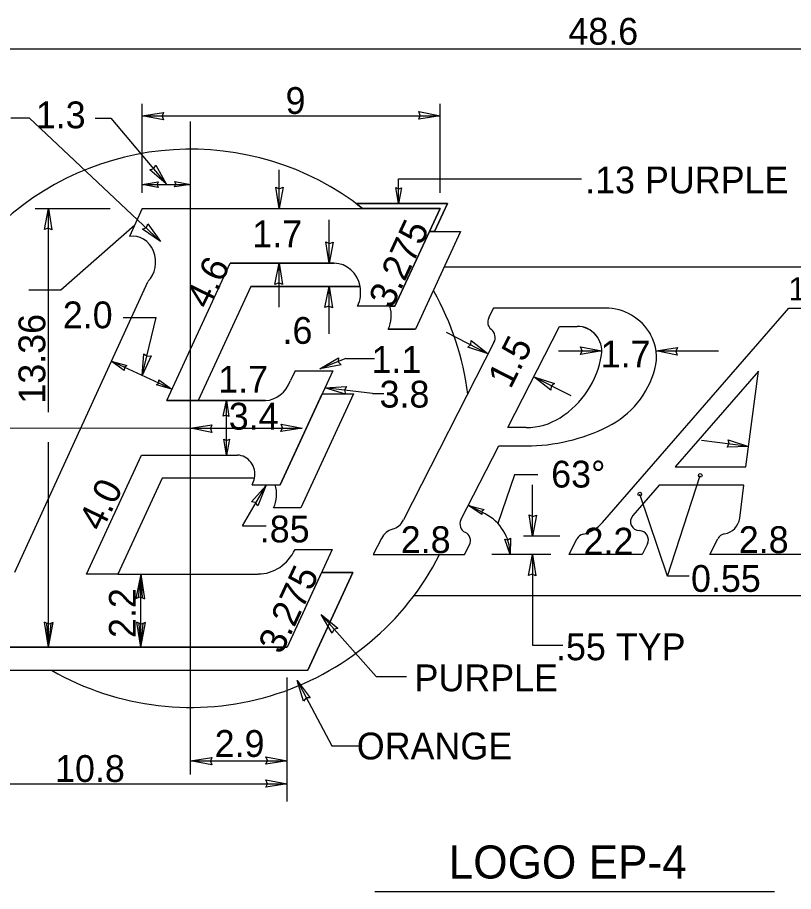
# Model space of a CAD drawing. Extents: x 10268197 to 10269179, y 2141503 to 2142677.
# Drawn here: x 10268503.98 to 10268524.24, y 2141999.29 to 2142022.12 of the extents above; entities that cross this region are included whole.
import ezdxf

# ---------------------------------------------------------------- set-up
doc = ezdxf.new("R2010")
doc.units = 0
for name, color, linetype in [('1', 7, 'Continuous'), ('21', 7, 'Continuous'), ('52', 7, 'Continuous'), ('NonPlottingEle_dp', 7, 'Continuous'), ('North Arrow', 7, 'Continuous')]:
    doc.layers.add(name, color=color, linetype=linetype)

msp = doc.modelspace()

# ---------------------------------------------------------------- linework, layer by layer
at = {"layer": '1'}
for p, q in [((10268499.274, 2142021.299), (10268540.97, 2142021.299)), ((10268507.237, 2142017.54), (10268507.237, 2142019.863)), ((10268515.011, 2142017.54), (10268515.011, 2142019.863)), ((10268506.005, 2142019.489), (10268506.417, 2142019.489)), ((10268506.417, 2142019.489), (10268507.862, 2142017.77)), ((10268507.237, 2142019.55), (10268515.011, 2142019.55)), ((10268508.5, 2142011.389), (10268508.5, 2142019.396)), ((10268510.808, 2142017.129), (10268510.808, 2142018.135)), ((10268507.237, 2142017.756), (10268508.5, 2142017.756)), ((10268513.926, 2142017.256), (10268513.926, 2142017.903)), ((10268513.926, 2142017.903), (10268518.702, 2142017.903)), ((10268504.437, 2142017.129), (10268506.399, 2142017.129)), ((10268504.789, 2142011.812), (10268504.789, 2142017.129)), ((10268512.99, 2142017.129), (10268512.824, 2142017.256)), ((10268512.824, 2142017.256), (10268515.208, 2142017.256)), ((10268515.011, 2142017.129), (10268512.99, 2142017.129)), ((10268514.733, 2142016.527), (10268515.011, 2142017.129)), ((10268515.208, 2142017.256), (10268514.871, 2142016.527)), ((10268505.111, 2142015.001), (10268507.044, 2142016.702)), ((10268512.115, 2142015.698), (10268512.115, 2142016.83)), ((10268513.832, 2142014.579), (10268514.733, 2142016.527)), ((10268515.55, 2142016.527), (10268514.371, 2142013.976)), ((10268514.733, 2142016.527), (10268515.55, 2142016.527)), ((10268514.733, 2142016.527), (10268515.55, 2142016.527)), ((10268514.871, 2142016.527), (10268514.733, 2142016.527)), ((10268507.878, 2142012.117), (10268509.53, 2142015.698)), ((10268509.53, 2142015.698), (10268512.248, 2142015.698)), ((10268510.808, 2142014.552), (10268510.808, 2142015.698)), ((10268510.071, 2142015.095), (10268508.694, 2142012.117)), ((10268510.071, 2142015.095), (10268512.925, 2142015.095)), ((10268512.925, 2142015.095), (10268510.581, 2142015.095)), ((10268512.115, 2142013.852), (10268512.115, 2142015.095)), ((10268504.276, 2142015.001), (10268505.111, 2142015.001)), ((10268513.702, 2142014.579), (10268513.832, 2142014.579)), ((10268506.737, 2142014.281), (10268507.602, 2142014.281)), ((10268507.231, 2142012.771), (10268507.602, 2142014.281)), ((10268514.371, 2142013.976), (10268513.66, 2142013.976)), ((10268515.173, 2142013.896), (10268516.272, 2142013.336)), ((10268512.555, 2142013.211), (10268511.875, 2142012.94)), ((10268512.555, 2142013.211), (10268513.297, 2142013.214)), ((10268518.106, 2142013.407), (10268519.236, 2142013.407)), ((10268520.654, 2142013.407), (10268522.28, 2142013.407)), ((10268508.013, 2142012.41), (10268506.423, 2142013.143)), ((10268517.461, 2142012.731), (10268518.423, 2142012.241)), ((10268510.836, 2142009.913), (10268511.933, 2142012.288)), ((10268512.75, 2142012.288), (10268511.376, 2142009.312)), ((10268511.933, 2142012.288), (10268512.75, 2142012.288)), ((10268513.245, 2142012.297), (10268512.008, 2142012.449)), ((10268513.245, 2142012.297), (10268513.54, 2142012.298)), ((10268508.694, 2142012.117), (10268507.878, 2142012.117)), ((10268509.433, 2142010.686), (10268509.433, 2142012.117)), ((10268508.5, 2142011.389), (10268501.211, 2142011.378)), ((10268508.5, 2142002.35), (10268508.5, 2142011.389)), ((10268508.5, 2142011.389), (10268511.416, 2142011.389)), ((10268504.789, 2142005.676), (10268504.789, 2142011.028)), ((10268523.068, 2142010.914), (10268521.837, 2142011.074)), ((10268505.783, 2142007.584), (10268507.216, 2142010.686)), ((10268507.216, 2142010.686), (10268509.722, 2142010.686)), ((10268507.757, 2142010.083), (10268506.6, 2142007.584)), ((10268510.167, 2142010.083), (10268507.757, 2142010.083)), ((10268516.956, 2142010.178), (10268516.523, 2142008.904)), ((10268517.567, 2142010.178), (10268516.956, 2142010.178)), ((10268520.947, 2142007.532), (10268521.805, 2142010.158)), ((10268509.853, 2142008.841), (10268510.459, 2142009.889)), ((10268510.709, 2142009.913), (10268510.836, 2142009.913)), ((10268517.427, 2142008.571), (10268517.427, 2142009.913)), ((10268520.947, 2142007.532), (10268520.227, 2142009.67)), ((10268516.19, 2142009.156), (10268515.753, 2142009.38)), ((10268511.376, 2142009.312), (10268510.665, 2142009.312)), ((10268509.853, 2142008.841), (10268510.475, 2142008.841)), ((10268518.142, 2142008.571), (10268517.189, 2142008.571)), ((10268517.904, 2142008.095), (10268516.364, 2142008.095)), ((10268517.427, 2142008.095), (10268517.427, 2142005.726)), ((10268506.6, 2142007.584), (10268505.783, 2142007.584)), ((10268507.195, 2142005.676), (10268507.195, 2142007.584)), ((10268511.917, 2142007.624), (10268511.018, 2142005.676)), ((10268511.557, 2142005.072), (10268512.735, 2142007.624)), ((10268512.735, 2142007.624), (10268511.917, 2142007.624)), ((10268521.517, 2142007.532), (10268520.947, 2142007.532)), ((10268511.905, 2142006.525), (10268513.346, 2142004.909)), ((10268511.018, 2142005.676), (10268503.181, 2142005.676)), ((10268517.427, 2142005.726), (10268518.22, 2142005.726)), ((10268502.902, 2142005.072), (10268511.557, 2142005.072)), ((10268511.018, 2142001.641), (10268511.018, 2142004.883)), ((10268511.282, 2142004.805), (10268512.189, 2142003.1)), ((10268513.346, 2142004.909), (10268514.139, 2142004.909)), ((10268512.189, 2142003.1), (10268512.982, 2142003.1)), ((10268508.5, 2142002.708), (10268511.018, 2142002.708)), ((10268501.784, 2142002.103), (10268511.018, 2142002.103))]:
    msp.add_line(p, q, dxfattribs=at)
msp.add_lwpolyline([(10268503.804, 2142019.493), (10268504.282, 2142019.493), (10268507.713, 2142016.27)], dxfattribs=at)
msp.add_lwpolyline([(10268512.824, 2142017.256), (10268512.99, 2142017.129), (10268515.011, 2142017.129), (10268514.733, 2142016.527), (10268514.871, 2142016.527), (10268515.208, 2142017.256)], close=True, dxfattribs=at)
for centre in [(10268521.805, 2142010.157), (10268520.226, 2142009.67)]:
    msp.add_circle(centre, 0.0476, dxfattribs=at)
msp.add_arc((10268515.649, 2142008.095), 1.191, 0, 62.9941, dxfattribs=at)
for centre, major_axis, start_param, end_param in [((10268512.247, 2142014.934), (0, 0.764), 4.924772, 6.283185), ((10268513.047, 2142014.332), (0, 0.764), 4.227342, 5.041732), ((10268509.721, 2142010.184), (0, 0.502), 4.510784, 6.283185), ((10268510.052, 2142009.667), (0, 0.764), 4.227342, 5.041732)]:
    msp.add_ellipse(centre, major_axis=major_axis, ratio=0.906667, start_param=start_param, end_param=end_param, dxfattribs=at)
at = {"layer": '21'}
msp.add_line((10268513.312, 2141999.294), (10268523.743, 2141999.294), dxfattribs=at)
at = {"layer": '52'}
for p, q in [((10268507.195, 2142007.584), (10268507.07, 2142006.942)), ((10268507.195, 2142007.584), (10268507.13, 2142006.967)), ((10268507.195, 2142007.584), (10268507.298, 2142006.938)), ((10268507.195, 2142007.584), (10268507.238, 2142006.965)), ((10268507.07, 2142006.942), (10268507.185, 2142006.989)), ((10268507.185, 2142006.989), (10268507.298, 2142006.938)), ((10268504.789, 2142005.676), (10268504.687, 2142006.323)), ((10268504.799, 2142006.271), (10268504.687, 2142006.323)), ((10268504.789, 2142005.676), (10268504.746, 2142006.295)), ((10268504.789, 2142005.676), (10268504.914, 2142006.319)), ((10268504.789, 2142005.676), (10268504.854, 2142006.294)), ((10268504.914, 2142006.319), (10268504.799, 2142006.271)), ((10268507.195, 2142005.676), (10268507.093, 2142006.323)), ((10268507.205, 2142006.271), (10268507.093, 2142006.323)), ((10268507.195, 2142005.676), (10268507.152, 2142006.295)), ((10268507.195, 2142005.676), (10268507.32, 2142006.319)), ((10268507.195, 2142005.676), (10268507.26, 2142006.294)), ((10268507.32, 2142006.319), (10268507.205, 2142006.271))]:
    msp.add_line(p, q, dxfattribs=at)
for points in [[(10268507.237, 2142019.55), (10268507.794, 2142019.637), (10268507.752, 2142019.542), (10268507.79, 2142019.443)], [(10268515.011, 2142019.55), (10268514.454, 2142019.462), (10268514.496, 2142019.557), (10268514.458, 2142019.656)], [(10268507.862, 2142017.77), (10268507.437, 2142018.139), (10268507.537, 2142018.169), (10268507.588, 2142018.262)], [(10268507.237, 2142017.756), (10268507.654, 2142017.822), (10268507.623, 2142017.75), (10268507.652, 2142017.676)], [(10268508.5, 2142017.756), (10268508.082, 2142017.691), (10268508.114, 2142017.762), (10268508.085, 2142017.836)], [(10268510.808, 2142017.129), (10268510.72, 2142017.686), (10268510.815, 2142017.644), (10268510.914, 2142017.682)], [(10268513.926, 2142017.256), (10268513.86, 2142017.674), (10268513.932, 2142017.642), (10268514.006, 2142017.671)], [(10268504.789, 2142017.129), (10268504.877, 2142016.573), (10268504.782, 2142016.615), (10268504.682, 2142016.577)], [(10268507.713, 2142016.27), (10268507.247, 2142016.587), (10268507.343, 2142016.628), (10268507.383, 2142016.726)], [(10268512.115, 2142015.698), (10268512.027, 2142016.255), (10268512.123, 2142016.213), (10268512.222, 2142016.251)], [(10268510.808, 2142015.698), (10268510.895, 2142015.142), (10268510.8, 2142015.184), (10268510.701, 2142015.146)], [(10268512.115, 2142015.095), (10268512.203, 2142014.538), (10268512.107, 2142014.58), (10268512.008, 2142014.542)], [(10268516.272, 2142013.336), (10268515.736, 2142013.51), (10268515.817, 2142013.576), (10268515.828, 2142013.682)], [(10268519.236, 2142013.407), (10268518.679, 2142013.319), (10268518.721, 2142013.415), (10268518.683, 2142013.514)], [(10268520.654, 2142013.407), (10268521.211, 2142013.495), (10268521.169, 2142013.4), (10268521.207, 2142013.3)], [(10268507.231, 2142012.771), (10268507.278, 2142013.332), (10268507.361, 2142013.268), (10268507.466, 2142013.282)], [(10268511.875, 2142012.94), (10268512.359, 2142013.227), (10268512.355, 2142013.123), (10268512.427, 2142013.045)], [(10268506.423, 2142013.143), (10268506.83, 2142013.028), (10268506.771, 2142012.976), (10268506.766, 2142012.896)], [(10268508.013, 2142012.41), (10268507.606, 2142012.525), (10268507.665, 2142012.577), (10268507.67, 2142012.656)], [(10268517.461, 2142012.731), (10268517.997, 2142012.556), (10268517.916, 2142012.491), (10268517.905, 2142012.385)], [(10268512.008, 2142012.449), (10268512.57, 2142012.477), (10268512.518, 2142012.386), (10268512.545, 2142012.284)], [(10268509.433, 2142012.117), (10268509.498, 2142011.7), (10268509.427, 2142011.732), (10268509.353, 2142011.703)], [(10268508.5, 2142011.389), (10268509.056, 2142011.477), (10268509.014, 2142011.382), (10268509.052, 2142011.283)], [(10268511.416, 2142011.389), (10268510.859, 2142011.302), (10268510.902, 2142011.397), (10268510.863, 2142011.496)], [(10268509.433, 2142010.686), (10268509.367, 2142011.104), (10268509.438, 2142011.072), (10268509.513, 2142011.101)], [(10268523.068, 2142010.914), (10268522.505, 2142010.899), (10268522.559, 2142010.988), (10268522.533, 2142011.091)], [(10268510.459, 2142009.889), (10268510.257, 2142009.364), (10268510.195, 2142009.448), (10268510.091, 2142009.465)], [(10268515.754, 2142009.373), (10268516.164, 2142009.268), (10268516.106, 2142009.215), (10268516.103, 2142009.135)], [(10268517.427, 2142008.571), (10268517.339, 2142009.127), (10268517.434, 2142009.085), (10268517.534, 2142009.123)], [(10268516.845, 2142008.098), (10268516.705, 2142008.496), (10268516.78, 2142008.479), (10268516.849, 2142008.52)], [(10268517.427, 2142008.095), (10268517.515, 2142007.538), (10268517.419, 2142007.58), (10268517.32, 2142007.542)], [(10268511.905, 2142006.525), (10268512.34, 2142006.168), (10268512.241, 2142006.136), (10268512.193, 2142006.042)], [(10268511.282, 2142004.805), (10268511.62, 2142004.355), (10268511.517, 2142004.347), (10268511.447, 2142004.267)], [(10268508.5, 2142002.708), (10268509.056, 2142002.796), (10268509.014, 2142002.701), (10268509.052, 2142002.602)], [(10268511.018, 2142002.708), (10268510.462, 2142002.621), (10268510.504, 2142002.716), (10268510.466, 2142002.815)], [(10268511.018, 2142002.103), (10268510.462, 2142002.015), (10268510.504, 2142002.11), (10268510.466, 2142002.209)]]:
    msp.add_lwpolyline(points, close=True, dxfattribs=at)
at = {"layer": 'NonPlottingEle_dp'}
for p, q in [((10268507.878, 2142012.117), (10268509.53, 2142015.698)), ((10268509.53, 2142015.698), (10268512.248, 2142015.698)), ((10268509.53, 2142015.698), (10268512.248, 2142015.698)), ((10268510.041, 2142015.698), (10268509.53, 2142015.698)), ((10268512.248, 2142015.698), (10268510.041, 2142015.698)), ((10268510.071, 2142015.095), (10268508.694, 2142012.117)), ((10268512.925, 2142015.095), (10268510.071, 2142015.095)), ((10268507.878, 2142012.117), (10268510.457, 2142012.117)), ((10268510.457, 2142012.117), (10268507.878, 2142012.117)), ((10268508.388, 2142012.117), (10268509.206, 2142012.117))]:
    msp.add_line(p, q, dxfattribs=at)
msp.add_ellipse((10268512.247, 2142014.934), major_axis=(0, 0.764), ratio=0.906667, start_param=4.924772, end_param=6.283185, dxfattribs=at)
at = {"layer": 'North Arrow'}
for p, q in [((10268507.237, 2142017.129), (10268506.901, 2142016.4)), ((10268507.237, 2142017.129), (10268515.011, 2142017.129)), ((10268512.824, 2142017.256), (10268515.208, 2142017.256)), ((10268515.011, 2142017.129), (10268513.832, 2142014.579)), ((10268515.208, 2142017.256), (10268514.871, 2142016.527)), ((10268515.55, 2142016.527), (10268514.371, 2142013.976)), ((10268514.733, 2142016.527), (10268515.55, 2142016.527)), ((10268507.878, 2142012.117), (10268509.53, 2142015.698)), ((10268509.53, 2142015.698), (10268512.248, 2142015.698)), ((10268540.97, 2142015.598), (10268515.12, 2142015.598)), ((10268503.908, 2142007.636), (10268507.382, 2142015.217)), ((10268510.071, 2142015.095), (10268508.694, 2142012.117)), ((10268512.925, 2142015.095), (10268510.071, 2142015.095)), ((10268513.832, 2142014.579), (10268512.86, 2142014.579)), ((10268516.412, 2142014.526), (10268516.281, 2142014.272)), ((10268519.33, 2142014.526), (10268516.412, 2142014.526)), ((10268519.257, 2142008.93), (10268524.121, 2142014.526)), ((10268524.121, 2142014.526), (10268524.978, 2142014.526)), ((10268513.66, 2142013.976), (10268514.371, 2142013.976)), ((10268516.785, 2142011.406), (10268518.133, 2142014.05)), ((10268516.785, 2142011.406), (10268518.133, 2142014.049)), ((10268518.133, 2142014.05), (10268518.593, 2142014.05)), ((10268518.133, 2142014.049), (10268518.593, 2142014.049)), ((10268516.419, 2142013.626), (10268514.061, 2142008.996)), ((10268512.212, 2142012.891), (10268510.836, 2142009.913)), ((10268511.225, 2142012.891), (10268511.109, 2142012.638)), ((10268511.225, 2142012.891), (10268512.212, 2142012.891)), ((10268523.324, 2142012.883), (10268521.148, 2142010.381)), ((10268523.324, 2142012.882), (10268521.148, 2142010.381)), ((10268522.998, 2142010.381), (10268523.324, 2142012.883)), ((10268522.998, 2142010.381), (10268523.324, 2142012.882)), ((10268512.75, 2142012.288), (10268511.376, 2142009.312)), ((10268511.933, 2142012.288), (10268512.75, 2142012.288)), ((10268507.878, 2142012.117), (10268510.457, 2142012.117)), ((10268510.457, 2142012.117), (10268507.878, 2142012.117)), ((10268517.257, 2142011.406), (10268516.785, 2142011.406)), ((10268517.257, 2142011.406), (10268516.785, 2142011.406)), ((10268515.557, 2142008.996), (10268516.543, 2142010.929)), ((10268516.543, 2142010.929), (10268517.257, 2142010.929)), ((10268505.783, 2142007.584), (10268507.216, 2142010.686)), ((10268507.216, 2142010.686), (10268509.722, 2142010.686)), ((10268521.148, 2142010.381), (10268522.998, 2142010.381)), ((10268521.148, 2142010.381), (10268522.998, 2142010.381)), ((10268507.757, 2142010.083), (10268506.6, 2142007.584)), ((10268510.167, 2142010.083), (10268507.757, 2142010.083)), ((10268510.105, 2142009.913), (10268510.836, 2142009.913)), ((10268520.736, 2142009.904), (10268520.045, 2142009.11)), ((10268522.948, 2142009.904), (10268520.736, 2142009.904)), ((10268522.836, 2142009.044), (10268522.948, 2142009.904)), ((10268511.376, 2142009.312), (10268510.665, 2142009.312)), ((10268513.482, 2142008.514), (10268513.268, 2142008.094)), ((10268518.38, 2142008.094), (10268518.587, 2142008.502)), ((10268522.056, 2142008.094), (10268522.267, 2142008.507)), ((10268512.197, 2142008.228), (10268511.018, 2142005.676)), ((10268511.225, 2142008.228), (10268512.197, 2142008.228)), ((10268515.649, 2142008.094), (10268515.779, 2142008.349)), ((10268520.426, 2142008.369), (10268520.286, 2142008.094)), ((10268513.268, 2142008.094), (10268515.649, 2142008.094)), ((10268520.286, 2142008.094), (10268518.38, 2142008.094)), ((10268524.438, 2142008.094), (10268522.056, 2142008.094)), ((10268506.6, 2142007.584), (10268505.783, 2142007.584)), ((10268506.6, 2142007.584), (10268510.265, 2142007.584)), ((10268512.735, 2142007.624), (10268511.557, 2142005.072)), ((10268511.917, 2142007.624), (10268512.735, 2142007.624)), ((10268514.335, 2142007.022), (10268536.601, 2142007.022)), ((10268501.759, 2142005.676), (10268511.018, 2142005.676)), ((10268502.902, 2142005.072), (10268511.557, 2142005.072))]:
    msp.add_line(p, q, dxfattribs=at)
for centre, radius, start, end in [((10268508.5, 2142011.389), 7.288, 51.9618, 218.2529), ((10268508.5, 2142011.389), 7.288, 7.0123, 29.4243), ((10268519.329, 2142013.168), 1.358, 29.4315, 90), ((10268516.494, 2142014.163), 0.238, 152.9784, 231.1602), ((10268516.165, 2142013.755), 0.286, 333.0027, 51.1602), ((10268518.592, 2142013.407), 0.643, 351.076, 90), ((10268518.592, 2142013.406), 0.643, 351.076, 90), ((10268519.474, 2142013.25), 1.191, 344.7074, 29.4315), ((10268516.874, 2142013.676), 2.382, 302.4206, 351.076), ((10268516.874, 2142013.676), 2.382, 302.4206, 351.076), ((10268518.325, 2142013.564), 2.382, 296.6431, 344.7074), ((10268517.257, 2142013.073), 1.667, 270, 302.4206), ((10268517.257, 2142013.073), 1.667, 270, 302.4206), ((10268517.257, 2142015.693), 4.764, 270, 296.6431), ((10268520.224, 2142008.954), 0.238, 138.9824, 268.6869), ((10268513.636, 2142009.212), 0.476, 286.4317, 332.9959), ((10268515.77, 2142008.888), 0.238, 152.9884, 244.7832), ((10268518.537, 2142009.556), 0.953, 282.7162, 318.9966), ((10268522.364, 2142009.105), 0.476, 279.2397, 352.5632), ((10268513.906, 2142008.298), 0.476, 106.4317, 152.9742), ((10268515.567, 2142008.457), 0.238, 333.0239, 64.7832), ((10268520.213, 2142008.478), 0.238, 332.9784, 88.6869), ((10268522.479, 2142008.4), 0.238, 99.2397, 153.0239), ((10268518.799, 2142008.394), 0.238, 102.7162, 153.0239), ((10268508.5, 2142011.389), 7.288, 240.0889, 333.1198)]:
    msp.add_arc(centre, radius, start, end, dxfattribs=at)
for centre, major_axis, ratio, start_param, end_param in [((10268506.981, 2142015.727), (0, 0.68), 0.889671, 3.865417, 6.41824), ((10268512.247, 2142014.934), (0, 0.764), 0.906667, 4.924065, 6.283185), ((10268512.247, 2142014.934), (0, 0.764), 0.906667, 4.924772, 6.283185), ((10268512.247, 2142014.934), (0, 0.764), 0.906667, 4.228038, 4.924065), ((10268513.047, 2142014.332), (0, 0.764), 0.906667, 4.227342, 5.041732), ((10268510.458, 2142013.073), (0, 0.955), 0.764971, 3.141593, 4.241405), ((10268509.721, 2142010.184), (0, 0.502), 0.906667, 4.510784, 6.283185), ((10268509.721, 2142010.184), (0, 0.502), 0.906667, 4.144801, 4.510784), ((10268510.052, 2142009.667), (0, 0.764), 0.906667, 4.227342, 5.041732), ((10268510.265, 2142008.778), (0, 1.193), 0.906667, 3.141593, 4.233038)]:
    msp.add_ellipse(centre, major_axis=major_axis, ratio=ratio, start_param=start_param, end_param=end_param, dxfattribs=at)

# ---------------------------------------------------------------- texts
at = {"layer": '1'}
for s, height, p in [('48.6', 0.7, (10268518.363, 2142021.405)), ('9', 0.7, (10268510.978, 2142019.597)), ('1.3', 0.7, (10268504.456, 2142019.222)), ('.13 PURPLE', 0.7, (10268518.801, 2142017.522)), ('1.7', 0.7, (10268510.11, 2142016.115)), ('1.0', 0.6037, (10268524.111, 2142014.729)), ('2.0', 0.7, (10268505.162, 2142014)), ('.6', 0.7, (10268510.899, 2142013.594)), ('1.7', 0.7, (10268519.207, 2142012.978)), ('1.1', 0.7, (10268513.223, 2142012.834)), ('1.7', 0.7, (10268509.22, 2142012.318)), ('3.8', 0.7, (10268513.433, 2142011.93)), ('3.4', 0.7, (10268509.495, 2142011.354)), ('63°', 0.7, (10268517.914, 2142009.842)), ('.85', 0.7, (10268510.305, 2142008.409)), ('2.8', 0.7, (10268513.986, 2142008.131)), ('2.2', 0.7, (10268518.759, 2142008.091)), ('2.8', 0.7, (10268522.813, 2142008.131)), ('0.55', 0.7, (10268521.565, 2142007.118)), ('.55 TYP', 0.7, (10268518.04, 2142005.333)), ('PURPLE', 0.7, (10268514.346, 2142004.522)), ('2.9', 0.7, (10268509.127, 2142002.809)), ('ORANGE', 0.7, (10268512.838, 2142002.743)), ('10.8', 0.7, (10268504.96, 2142002.155)), ('LOGO EP-4', 0.8624, (10268515.238, 2141999.634))]:
    msp.add_text(s, height=height, dxfattribs=at).set_placement(p)
for s, rotation, p in [('3.275', 65.0602, (10268513.757, 2142014.489)), ('4.6', 64.0244, (10268508.971, 2142014.468)), ('13.36', 90, (10268504.705, 2142012.032)), ('1.5', 62.9907, (10268516.852, 2142012.394)), ('4.0', 64.0244, (10268506.177, 2142008.668)), ('3.275', 65.0602, (10268510.874, 2142005.462)), ('2.2', 90, (10268507.068, 2142005.914))]:
    msp.add_text(s, height=0.7, rotation=rotation, dxfattribs=at).set_placement(p)

doc.saveas('drawing.dxf')
